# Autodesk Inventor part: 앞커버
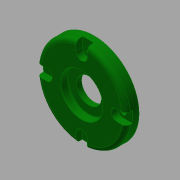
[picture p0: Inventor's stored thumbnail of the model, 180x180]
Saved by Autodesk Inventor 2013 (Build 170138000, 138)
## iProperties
Created: 2019-01
Part Number: 앞커버
Material: 알루미늄 6061
Document SubType Name: Modeling
Designer: mduedu
Density: 1 g/cm^3
Author: mduedu
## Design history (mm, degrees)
sketch "스케치1"
  geometry: L1 (0, 0)-(9, 0); L2 (9, 0)-(9, 32); L3 (9, 32)-(0, 32); L4 (0, 32)-(0, 0); L5 (9, 0)-(12, 0); L6 (12, 0)-(12, 20); L7 (12, 20)-(9, 20); L8 (9, 20)-(9, 0)
  constraints: 16 end point, 4 parallel, 2 horizontal, 2 perpendicular
  dimensions: "d0" = 12 distance between parallel lines of L6 L4; "d2" = 64 diameter of L3 L1; "d3" = 40 diameter of L7 L5; "d4" = 3 distance between parallel lines of L6 L2
revolve "회전1" sketch "스케치1" stored, may be unused: angle "d5" = 90 deg
sketch "스케치2"
  geometry: L1 (0, -32)-(0, 32) reference; L2 (0, 32)-(9, 32) reference; L3 (9, 32)-(9, 20) reference; L4 (9, 20)-(12, 20) reference; L5 (12, 20)-(12, -20) reference; L6 (12, -20)-(9, -20) reference; L7 (9, -20)-(9, -32) reference; L8 (9, -32)-(0, -32) reference; L9 (0, 0)-(5.2, 0); L10 (5.2, 0)-(5.2, 15); L11 (5.2, 15)-(0, 15); L12 (0, 15)-(0, 0); L13 (5.2, 0)-(9, 0); L14 (9, 0)-(9, 9); L15 (9, 9)-(5.2, 9); L16 (5.2, 9)-(5.2, 0); L17 (9, 0)-(12, 0); L18 (12, 0)-(12, 15); L19 (12, 15)-(9, 15); L20 (9, 15)-(9, 0)
  constraints: 24 end point, 6 parallel, 3 horizontal, 3 perpendicular, 1 point on line
  dimensions: "d6" = 3 distance of L18.end L19.end; "d8" = 5.2 distance of L10.end L11.end; "d9" = 30 diameter of L11 L9; "d10" = 18 diameter of L15 L13; "d11" = 30 diameter of L19 L17
revolve "회전2" sketch "스케치2" stored, may be unused: angle "d12" = 90 deg
chamfer "모따기1" distance "d13" = 0.5; stored, may be unused: second distance "d14" = 2, angle "d15" = 30 deg
fillet "모깎기1" dims "d16" = 0.5
fillet "모깎기2" dims "d17" = 3
fillet "모깎기3" dims "d18" = 3
chamfer "모따기2" distance "d24" = 1; stored, may be unused: second distance "d25" = 2, angle "d26" = 45 deg
sketch "스케치3" dims "d19" = 50
  geometry: 6 further points
  constraints: 2 vertical alignment, 1 coincident, 7 other
  dimensions: "d22" = 360 deg dimension on point (0, 0) point (0, 25) (derived)
sketch "스케치4"
  geometry: 4 further points
  constraints: 4 other
hole "구멍1" sketch "스케치4" at (-25, 0), (0, -25), (25, 0), (0, 25) diameter "d27" = 4.5; stored, may be unused: countersink angle "d31" = 90 deg, drill point angle "d33" = 0 deg; dims "d28" = 6, "d29" = 8, "d30" = 4.6, "d32" = 8
sketch "스케치5"
  geometry: L1 (-4, 0)-(-4, 6.749); L2 (4, 0)-(4, 6.749); A1 r 4 centre (0, 0) between (0, 4) and (-4, 0) reference; A2 r 32 centre (0, -25) between (-4, 6.749) and (4, 6.749) reference; A3 r 4 centre (0, 0) between (-4, 0) and (4, 0); A4 r 32 centre (0, -25) between (4, 6.749) and (-4, 6.749); A5 r 4 centre (0, 0) between (4, 0) and (-4, 0); 1 further point
  constraints: 10 point on circle, 4 end point, 3 centre point, 2 coincident, 2 tangent, 1 parallel, 1 vertical
extrude "돌출1" cut sketch "스케치5" stored distance "d34" = 10; taper "d35" = 0 deg
node "솔리드1"
pattern_circular "원형 패턴1" dims angle "d37" = 360 deg
node "절단 모서리 투영1"
